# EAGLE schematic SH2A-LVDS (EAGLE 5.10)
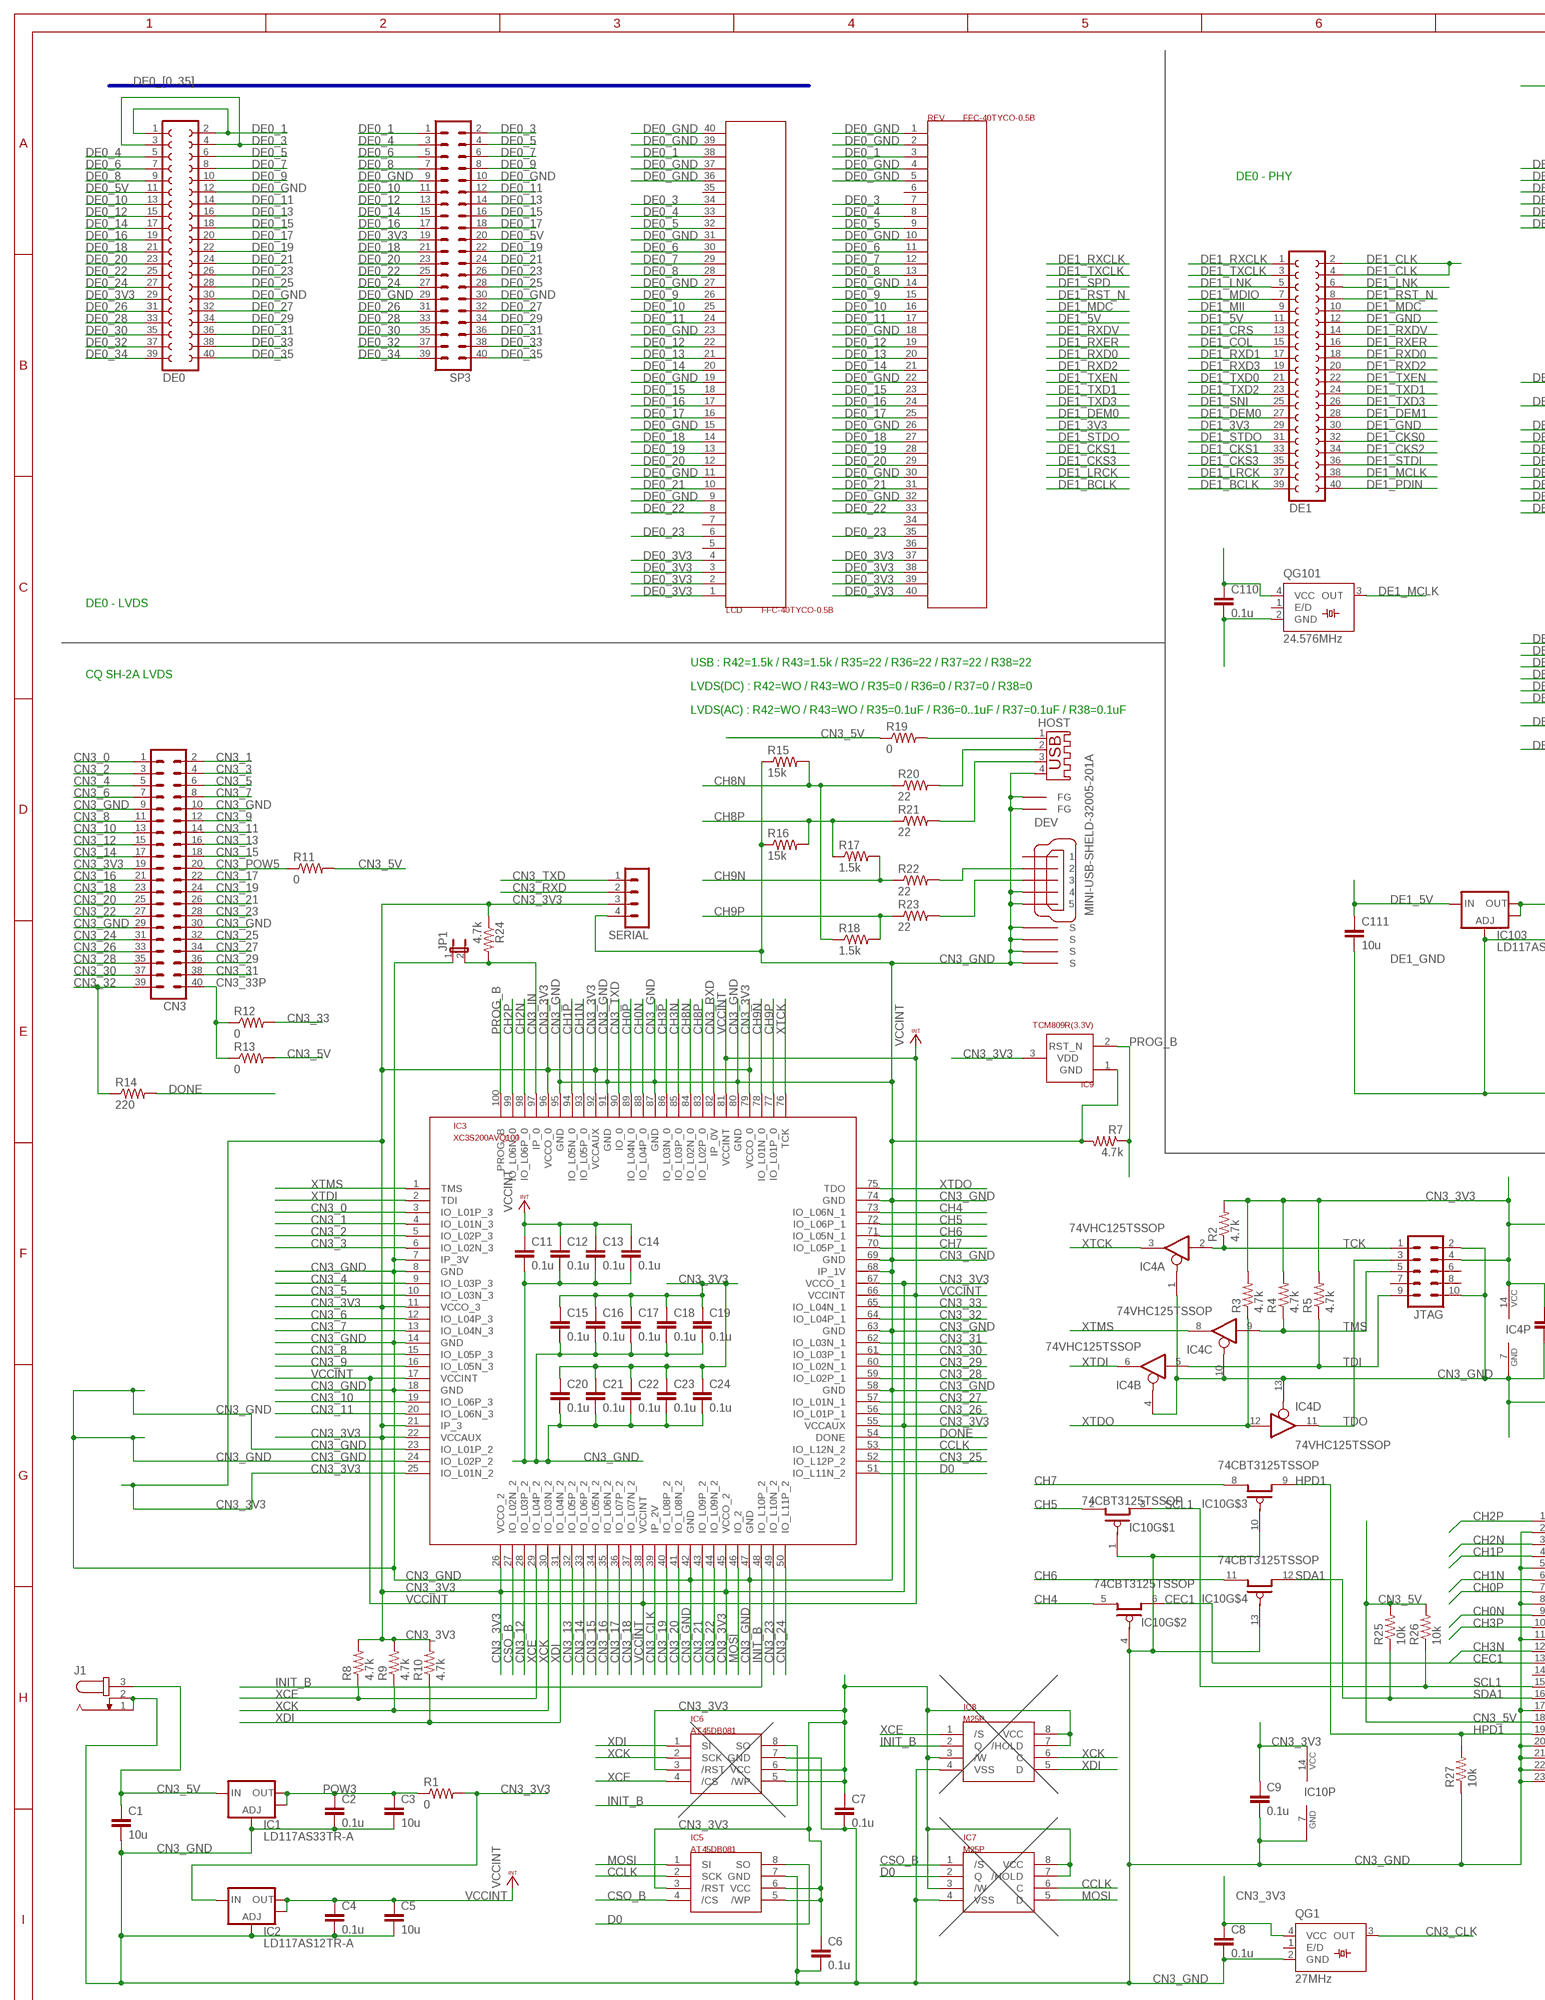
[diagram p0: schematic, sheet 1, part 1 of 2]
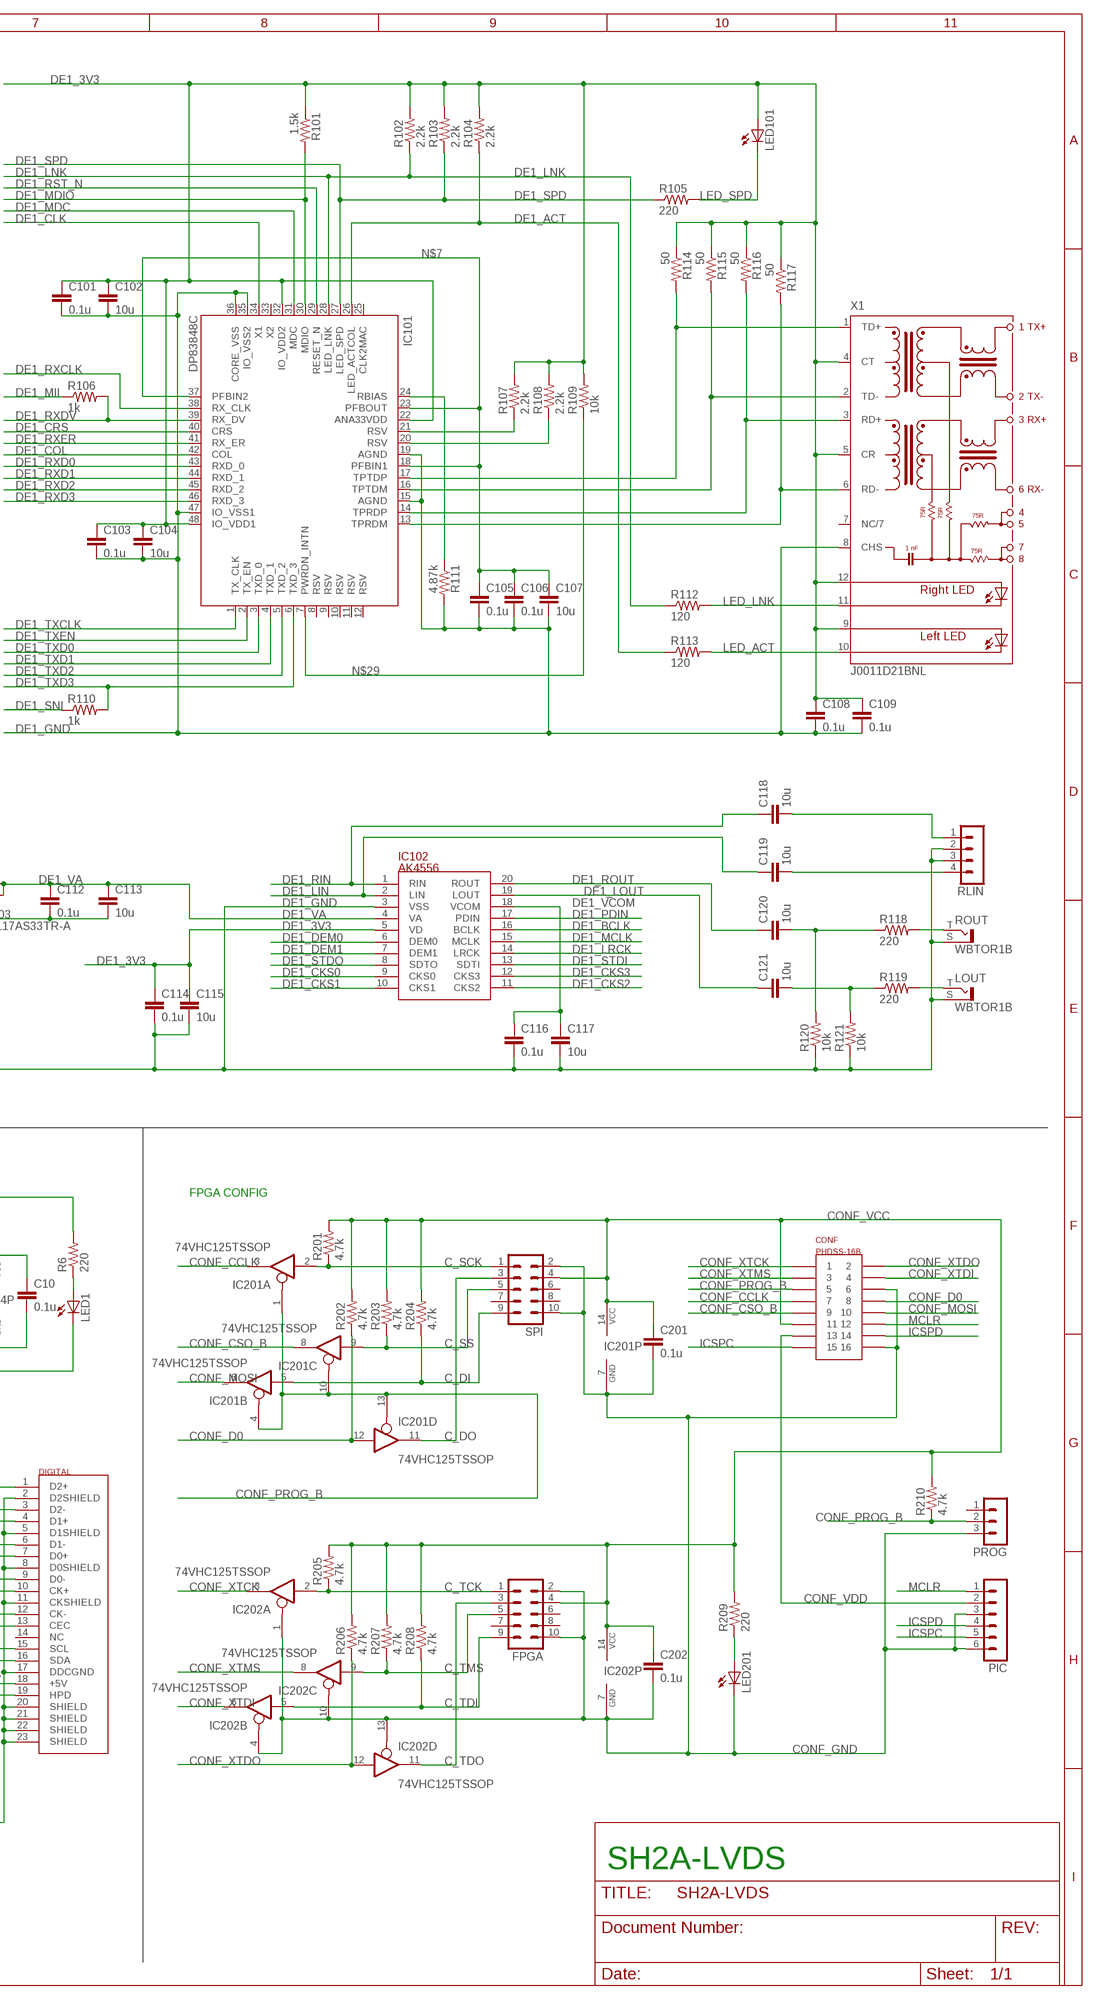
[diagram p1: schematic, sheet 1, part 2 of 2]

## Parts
C1  10u  C-EUC2012  [C2012]
C2  0.1u  C-EUC1608  [C1608]
C3  10u  C-EUC2012  [C2012]
C4  0.1u  C-EUC1608  [C1608]
C5  10u  C-EUC2012  [C2012]
C6  0.1u  C-EUC1608  [C1608]
C7  0.1u  C-EUC1608  [C1608]
C8  0.1u  C-EUC1608  [C1608]
C9  0.1u  C-EUC1608  [C1608]
C10  0.1u  C-EUC1608  [C1608]
C11  0.1u  C-EUC1608  [C1608]
C12  0.1u  C-EUC1608  [C1608]
C13  0.1u  C-EUC1608  [C1608]
C14  0.1u  C-EUC1608  [C1608]
C15  0.1u  C-EUC1608  [C1608]
C16  0.1u  C-EUC1608  [C1608]
C17  0.1u  C-EUC1608  [C1608]
C18  0.1u  C-EUC1608  [C1608]
C19  0.1u  C-EUC1608  [C1608]
C20  0.1u  C-EUC1608  [C1608]
C21  0.1u  C-EUC1608  [C1608]
C22  0.1u  C-EUC1608  [C1608]
C23  0.1u  C-EUC1608  [C1608]
C24  0.1u  C-EUC1608  [C1608]
C101  0.1u  C-EUC1608  [C1608]
C102  10u  C-EUC2012  [C2012]
C103  0.1u  C-EUC1608  [C1608]
C104  10u  C-EUC2012  [C2012]
C105  0.1u  C-EUC1608  [C1608]
C106  0.1u  C-EUC1608  [C1608]
C107  10u  C-EUC2012  [C2012]
C108  0.1u  C-EUC1608  [C1608]
C109  0.1u  C-EUC1608  [C1608]
C110  0.1u  C-EUC1608  [C1608]
C111  10u  C-EUC2012  [C2012]
C112  0.1u  C-EUC1608  [C1608]
C113  10u  C-EUC2012  [C2012]
C114  0.1u  C-EUC1608  [C1608]
C115  10u  C-EUC2012  [C2012]
C116  0.1u  C-EUC1608  [C1608]
C117  10u  C-EUC2012  [C2012]
C118  10u  C-EUC2012  [C2012]
C119  10u  C-EUC2012  [C2012]
C120  10u  C-EUC2012  [C2012]
C121  10u  C-EUC2012  [C2012]
C201  0.1u  C-EUC1608  [C1608]
C202  0.1u  C-EUC1608  [C1608]
CN3  MA20-2  [MA20-2]
CONF  PHDSS-16B  [PHDSS-16]
DE0  FE20-2  [FE20-2]
DE1  FE20-2  [FE20-2]
DEV  MINI-USB-SHELD-32005-201A  [32005-201A]
DIGITAL  HDMIHDMI-FCI-A  [HDMI-FCI-A-UPDATE]
FPGA  ML10  [ML10]
HOST  USB-A003FG  [USB]
IC1  LD117AS33TR-A  LD117AS-A  [SOT223]
IC2  LD117AS12TR-A  LD117AS-A  [SOT223]
IC3  XC3S200AVQ100  XC3S50AVQ100  [VQ100]
IC4  74VHC125TSSOP  74125TSSOP  [PW_R-PDSO-G14]
IC5  AT45DB081  AT45DB  [AT45DB]
IC6  AT45DB081  AT45DB  [AT45DB]
IC7  M25P  [AT45DB]
IC8  M25P  [AT45DB]
IC9  TCM809R(3.3V)  TCM809  [SOT23]
IC10  74CBT3125TSSOP  [PW_R-PDSO-G14]
IC101  DP83848C  [LQFP48]
IC102  AK4556  [SSOP20]
IC103  LD117AS33TR-A  LD117AS-A  [SOT223]
IC201  74VHC125TSSOP  74125TSSOP  [PW_R-PDSO-G14]
IC202  74VHC125TSSOP  74125TSSOP  [PW_R-PDSO-G14]
J1  JACK-PLUG0A  [SPC4077A]
JP1  JP1EA  [JP1A]
JTAG  ML10  [ML10]
LCD  FFC-40TYCO-0.5B  [FFC-40-0.5B-TYCO]
LED1  LED5MM  [LED5MM]
LED101  LED5MM  [LED5MM]
LED201  LED5MM  [LED5MM]
LOUT  WBTOR1B  [WBTOR1B]
PIC  MA06-1A  [MA06-1A]
PROG  MA03-1MA03-1A  [MA03-1A]
QG1  27MHz  SM77H  [SM77H]
QG101  24.576MHz  SM77H  [SM77H]
R1  0  R-US_R0603  [R0603]
R2  4.7k  R-US_R0603  [R0603]
R3  4.7k  R-US_R0603  [R0603]
R4  4.7k  R-US_R0603  [R0603]
R5  4.7k  R-US_R0603  [R0603]
R6  220  R-US_R0603  [R0603]
R7  4.7k  R-US_R0603  [R0603]
R8  4.7k  R-US_R0603  [R0603]
R9  4.7k  R-US_R0603  [R0603]
R10  4.7k  R-US_R0603  [R0603]
R11  0  R-US_R0603  [R0603]
R12  0  R-US_R0603  [R0603]
R13  0  R-US_R0603  [R0603]
R14  220  R-US_R0603  [R0603]
R15  15k  R-US_R0603  [R0603]
R16  15k  R-US_R0603  [R0603]
R17  1.5k  R-US_R0603  [R0603]
R18  1.5k  R-US_R0603  [R0603]
R19  0  R-US_R0603  [R0603]
R20  22  R-US_R0603  [R0603]
R21  22  R-US_R0603  [R0603]
R22  22  R-US_R0603  [R0603]
R23  22  R-US_R0603  [R0603]
R24  4.7k  R-US_R0603  [R0603]
R25  10k  R-US_R0603  [R0603]
R26  10k  R-US_R0603  [R0603]
R27  10k  R-US_R0603  [R0603]
R101  1.5k  R-US_R0603  [R0603]
R102  2.2k  R-US_R0603  [R0603]
R103  2.2k  R-US_R0603  [R0603]
R104  2.2k  R-US_R0603  [R0603]
R105  220  R-US_R0603  [R0603]
R106  1k  R-US_R0603  [R0603]
R107  2.2k  R-US_R0603  [R0603]
R108  2.2k  R-US_R0603  [R0603]
R109  10k  R-US_R0603  [R0603]
R110  1k  R-US_R0603  [R0603]
R111  4.87k  R-US_R0603  [R0603]
R112  120  R-US_R0603  [R0603]
R113  120  R-US_R0603  [R0603]
R114  50  R-US_R0603  [R0603]
R115  50  R-US_R0603  [R0603]
R116  50  R-US_R0603  [R0603]
R117  50  R-US_R0603  [R0603]
R118  220  R-US_R0603  [R0603]
R119  220  R-US_R0603  [R0603]
R120  10k  R-US_R0603  [R0603]
R121  10k  R-US_R0603  [R0603]
R201  4.7k  R-US_R0603  [R0603]
R202  4.7k  R-US_R0603  [R0603]
R203  4.7k  R-US_R0603  [R0603]
R204  4.7k  R-US_R0603  [R0603]
R205  4.7k  R-US_R0603  [R0603]
R206  4.7k  R-US_R0603  [R0603]
R207  4.7k  R-US_R0603  [R0603]
R208  4.7k  R-US_R0603  [R0603]
R209  220  R-US_R0603  [R0603]
R210  4.7k  R-US_R0603  [R0603]
REV  FFC-40TYCO-0.5B  [FFC-40-0.5B-TYCO]
RLIN  MA04-1A  [MA04-1A]
ROUT  WBTOR1B  [WBTOR1B]
SERIAL  MA04-1A  [MA04-1A]
SP3  MA20-2  [MA20-2]
SPI  ML10  [ML10]
X1  J0011D21BNL  [J0B]

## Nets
C_DI: IC201.5(B:I) R204.1 SPI.9
C_DO: IC201.11(D:O) SPI.3
C_SCK: IC201.2(A:I) R201.1 SPI.1
C_SS: IC201.9(C:I) R203.1 SPI.5
C_TCK: FPGA.1 IC202.2(A:I) R205.1
C_TDI: FPGA.9 IC202.5(B:I) R208.1
C_TDO: FPGA.3 IC202.11(D:O)
C_TMS: FPGA.5 IC202.9(C:I) R207.1
CCLK: IC3.53(IO_L12N_2) IC5.2(SCK) IC7.6(C)
CEC1: DIGITAL.13(CEC) IC10.6(O)
CH0N: DIGITAL.9(D0-) IC3.88(IO_L04P_0)
CH0P: DIGITAL.7(D0+) IC3.89(IO_L04N_0)
CH1N: DIGITAL.6(D1-) IC3.93(IO_L05P_0)
CH1P: DIGITAL.4(D1+) IC3.94(IO_L05N_0)
CH2N: DIGITAL.3(D2-) IC3.98(IO_L06P_0)
CH2P: DIGITAL.1(D2+) IC3.99(IO_L06N_0)
CH3N: DIGITAL.12(CK-) IC3.85(IO_L03P_0)
CH3P: DIGITAL.10(CK+) IC3.86(IO_L03N_0)
CH4: IC3.73(IO_L06N_1) IC10.5(I)
CH5: IC3.72(IO_L06P_1) IC10.2(I)
CH6: IC3.71(IO_L05N_1) IC10.11(O)
CH7: IC3.70(IO_L05P_1) IC10.8(O)
CH8N: IC3.84(IO_L02N_0) R15.2 R18.1 R20.1
CH8P: IC3.83(IO_L02P_0) R16.2 R17.1 R21.1
CH9N: IC3.78(IO_L01N_0) R17.2 R22.1
CH9P: IC3.77(IO_L01P_0) R18.2 R23.1
CN3_0: CN3.1 IC3.3(IO_L01P_3)
CN3_1: CN3.2 IC3.4(IO_L01N_3)
CN3_2: CN3.3 IC3.5(IO_L02P_3)
CN3_3: CN3.4 IC3.6(IO_L02N_3)
CN3_3V3: C6.1 C7.1 C8.1 C9.1 C10.1 C15.1 C16.1 C17.1 C18.1 C19.1 C20.1 C21.1 C22.1 C23.1 C24.1 CN3.19 IC2.3(IN) IC3.11(VCCO_3) IC3.21(IP_3) IC3.22(VCCAUX) IC3.25(IO_L01N_2) IC3.26(VCCO_2) IC3.45(VCCO_2) IC3.55(VCCAUX) IC3.67(VCCO_1) IC3.79(VCCO_0) IC3.92(VCCAUX) IC3.96(VCCO_0) IC4.14(P:VCC) IC5.3(/RST) IC5.5(/WP) IC5.6(VCC) IC6.3(/RST) IC6.5(/WP) IC6.6(VCC) IC7.3(/W) IC7.7(/HOLD) IC7.8(VCC) IC8.3(/W) IC8.7(/HOLD) IC8.8(VCC) IC9.3(VDD) IC10.14(P:VCC) JTAG.4 QG1.4(VCC) R1.2 R2.2 R3.2 R4.2 R5.2 R6.2 R8.2 R9.2 R10.2 R24.1 SERIAL.3
CN3_4: CN3.5 IC3.9(IO_L03P_3)
CN3_5: CN3.6 IC3.10(IO_L03N_3)
CN3_5V: C1.1 DIGITAL.18(+5V) IC1.3(IN) J1.3 R11.2 R13.2 R19.1 R25.2 R26.2
CN3_6: CN3.7 IC3.12(IO_L04P_3)
CN3_7: CN3.8 IC3.13(IO_L04N_3)
CN3_8: CN3.11 IC3.15(IO_L05P_3)
CN3_9: CN3.12 IC3.16(IO_L05N_3)
CN3_10: CN3.13 IC3.19(IO_L06P_3)
CN3_11: CN3.14 IC3.20(IO_L06N_3)
CN3_12: CN3.15 IC3.28(IO_L03P_2)
CN3_13: CN3.16 IC3.32(IO_L05P_2)
CN3_14: CN3.17 IC3.33(IO_L06P_2)
CN3_15: CN3.18 IC3.34(IO_L05N_2)
CN3_16: CN3.21 IC3.35(IO_L06N_2)
CN3_17: CN3.22 IC3.36(IO_L07P_2)
CN3_18: CN3.23 IC3.37(IO_L07N_2)
CN3_19: CN3.24 IC3.40(IO_L08P_2)
CN3_20: CN3.25 IC3.41(IO_L08N_2)
CN3_21: CN3.26 IC3.43(IO_L09P_2)
CN3_22: CN3.27 IC3.44(IO_L09N_2)
CN3_23: CN3.28 IC3.49(IO_L10N_2)
CN3_24: CN3.31 IC3.50(IO_L11P_2)
CN3_25: CN3.32 IC3.52(IO_L12P_2)
CN3_26: CN3.33 IC3.56(IO_L01P_1)
CN3_27: CN3.34 IC3.57(IO_L01N_1)
CN3_28: CN3.35 IC3.59(IO_L02P_1)
CN3_29: CN3.36 IC3.60(IO_L02N_1)
CN3_30: CN3.37 IC3.61(IO_L03P_1)
CN3_31: CN3.38 IC3.62(IO_L03N_1)
CN3_32: CN3.39 IC3.64(IO_L04P_1) R14.1
CN3_33: IC3.65(IO_L04N_1) R12.2
CN3_33P: CN3.40 R12.1 R13.1
CN3_CLK: IC3.39(IP_2V) QG1.3(OUT)
CN3_GND: C1.2 C2.2 C3.2 C4.2 C5.2 C6.2 C7.2 C8.2 C9.2 C10.2 C11.2 C12.2 C13.2 C14.2 C15.2 C16.2 C17.2 C18.2 C19.2 C20.2 C21.2 C22.2 C23.2 C24.2 CN3.9 CN3.10 CN3.29 CN3.30 DEV.4 DEV.5 DEV.M1(S) DEV.M2(S) DEV.M3(S) DEV.M4(S) DIGITAL.2(D2SHIELD) DIGITAL.5(D1SHIELD) DIGITAL.8(D0SHIELD) DIGITAL.11(CKSHIELD) DIGITAL.17(DDCGND) DIGITAL.20(SHIELD) DIGITAL.21(SHIELD) DIGITAL.22(SHIELD) DIGITAL.23(SHIELD) HOST.4 HOST.P$1(FG) HOST.P$2(FG) IC1.1(ADJ) IC2.1(ADJ) IC3.7(IP_3V) IC3.8(GND) IC3.14(GND) IC3.18(GND) IC3.23(IO_L01P_2) IC3.24(IO_L02P_2) IC3.42(GND) IC3.47(GND) IC3.58(GND) IC3.63(GND) IC3.68(IP_1V) IC3.69(GND) IC3.74(GND) IC3.80(GND) IC3.87(GND) IC3.91(GND) IC3.95(GND) IC4.1(A:OE) IC4.4(B:OE) IC4.7(P:GND) IC4.10(C:OE) IC4.13(D:OE) IC5.7(GND) IC6.7(GND) IC7.4(VSS) IC8.4(VSS) IC9.1(GND) IC10.1(OE) IC10.4(OE) IC10.7(P:GND) IC10.10(OE) IC10.13(OE) J1.1 J1.2 JP1.1 JTAG.2 JTAG.10 LED1.K(C) QG1.2(GND) R7.2 R15.1 R16.1 R27.1 SERIAL.4
CN3_IN: IC3.97(IP_0) JP1.2 R24.2
CN3_POW5: CN3.20 R11.1
CN3_RXD: IC3.82(IP_0V) SERIAL.2
CN3_TXD: IC3.90(IO_0) SERIAL.1
CONF_CCLK: CONF.P$7 IC201.3(A:O)
CONF_CSO_B: CONF.P$9 IC201.8(C:O)
CONF_D0: CONF.P$8 IC201.12(D:I) R202.1
CONF_GND: C201.2 C202.2 CONF.P$6 CONF.P$16 FPGA.2 FPGA.10 IC201.7(P:GND) IC202.1(A:OE) IC202.4(B:OE) IC202.7(P:GND) IC202.10(C:OE) IC202.13(D:OE) LED201.K(C) PIC.3 PIC.6 PROG.3 SPI.2 SPI.10
CONF_MOSI: CONF.P$10 IC201.6(B:O)
CONF_PROG_B: CONF.P$5 IC201.1(A:OE) IC201.4(B:OE) IC201.10(C:OE) IC201.13(D:OE) PROG.2 R210.1
CONF_VCC: C201.1 C202.1 CONF.P$11 FPGA.4 IC201.14(P:VCC) IC202.14(P:VCC) R201.2 R202.2 R203.2 R204.2 R205.2 R206.2 R207.2 R208.2 R209.2 R210.2 SPI.4
CONF_VDD: CONF.P$13 PIC.2
CONF_XTCK: CONF.P$1 IC202.3(A:O)
CONF_XTDI: CONF.P$4 IC202.6(B:O)
CONF_XTDO: CONF.P$2 IC202.12(D:I) R206.1
CONF_XTMS: CONF.P$3 IC202.8(C:O)
CSO_B: IC3.27(IO_L02N_2) IC5.4(/CS) IC7.1(/S)
D0: IC3.51(IO_L11N_2) IC5.8(SO) IC7.2(Q)
DE0_1: DE0.1 DE0.2 LCD.38 REV.3 SP3.1
DE0_3: DE0.3 DE0.4 LCD.34 REV.7 SP3.2
DE0_3V3: DE0.29 LCD.1 LCD.2 LCD.3 LCD.4 REV.37 REV.38 REV.39 REV.40 SP3.19
DE0_4: DE0.5 LCD.33 REV.8 SP3.3
DE0_5: DE0.6 LCD.32 REV.9 SP3.4
DE0_5V: DE0.11 SP3.20
DE0_6: DE0.7 LCD.30 REV.11 SP3.5
DE0_7: DE0.8 LCD.29 REV.12 SP3.6
DE0_8: DE0.9 LCD.28 REV.13 SP3.7
DE0_9: DE0.10 LCD.26 REV.15 SP3.8
DE0_10: DE0.13 LCD.25 REV.16 SP3.11
DE0_11: DE0.14 LCD.24 REV.17 SP3.12
DE0_12: DE0.15 LCD.22 REV.19 SP3.13
DE0_13: DE0.16 LCD.21 REV.20 SP3.14
DE0_14: DE0.17 LCD.20 REV.21 SP3.15
DE0_15: DE0.18 LCD.18 REV.23 SP3.16
DE0_16: DE0.19 LCD.17 REV.24 SP3.17
DE0_17: DE0.20 LCD.16 REV.25 SP3.18
DE0_18: DE0.21 LCD.14 REV.27 SP3.21
DE0_19: DE0.22 LCD.13 REV.28 SP3.22
DE0_20: DE0.23 LCD.12 REV.29 SP3.23
DE0_21: DE0.24 LCD.10 REV.31 SP3.24
DE0_22: DE0.25 LCD.8 REV.33 SP3.25
DE0_23: DE0.26 LCD.6 REV.35 SP3.26
DE0_24: DE0.27 SP3.27
DE0_25: DE0.28 SP3.28
DE0_26: DE0.31 SP3.31
DE0_27: DE0.32 SP3.32
DE0_28: DE0.33 SP3.33
DE0_29: DE0.34 SP3.34
DE0_30: DE0.35 SP3.35
DE0_31: DE0.36 SP3.36
DE0_32: DE0.37 SP3.37
DE0_33: DE0.38 SP3.38
DE0_34: DE0.39 SP3.39
DE0_35: DE0.40 SP3.40
DE0_GND: DE0.12 DE0.30 LCD.9 LCD.11 LCD.15 LCD.19 LCD.23 LCD.27 LCD.31 LCD.36 LCD.37 LCD.39 LCD.40 REV.1 REV.2 REV.4 REV.5 REV.10 REV.14 REV.18 REV.22 REV.26 REV.30 REV.32 SP3.9 SP3.10 SP3.29 SP3.30
DE1_3V3: C101.1 C102.1 C103.1 C104.1 C108.1 C109.1 C110.1 C114.1 C115.1 DE1.29 IC101.22(ANA33VDD) IC101.32(IO_VDD2) IC101.48(IO_VDD1) IC102.5(VD) LED101.A QG101.4(VCC) R101.1 R102.2 R103.2 R104.2 R107.2 R108.2 R109.2 R114.1 R115.1 R116.1 R117.1 X1.4(CT) X1.5(CR) X1.9(A-L) X1.12(A-R)
DE1_5V: C111.1 DE1.11 IC103.3(IN)
DE1_ACT: IC101.26(LED_ACTCOL) R104.1 R113.1
DE1_BCLK: DE1.39 IC102.16(BCLK)
DE1_CKS0: DE1.32 IC102.9(CKS0)
DE1_CKS1: DE1.33 IC102.10(CKS1)
DE1_CKS2: DE1.34 IC102.11(CKS2)
DE1_CKS3: DE1.35 IC102.12(CKS3)
DE1_CLK: DE1.2 DE1.4 IC101.34(X1)
DE1_COL: DE1.15 IC101.42(COL)
DE1_CRS: DE1.13 IC101.40(CRS)
DE1_DEM0: DE1.27 IC102.6(DEM0)
DE1_DEM1: DE1.28 IC102.7(DEM1)
DE1_GND: C101.2 C102.2 C103.2 C104.2 C105.2 C106.2 C107.2 C108.2 C109.2 C110.2 C111.2 C112.2 C113.2 C114.2 C115.2 C116.2 C117.2 DE1.12 DE1.30 IC101.15(AGND) IC101.19(AGND) IC101.35(IO_VSS2) IC101.36(CORE_VSS) IC101.47(IO_VSS1) IC102.3(VSS) IC103.1(ADJ) LOUT.S QG101.2(GND) R111.2 R120.1 R121.1 RLIN.2 RLIN.3 ROUT.S X1.8(CHS)
DE1_LIN: C119.1 IC102.2(LIN)
DE1_LNK: DE1.5 DE1.6 IC101.28(LED_LNK) R102.1 R112.1
DE1_LOUT: C121.1 IC102.19(LOUT)
DE1_LRCK: DE1.37 IC102.14(LRCK)
DE1_MCLK: DE1.38 IC102.15(MCLK) QG101.3(OUT)
DE1_MDC: DE1.10 IC101.31(MDC)
DE1_MDIO: DE1.7 IC101.30(MDIO) R101.2
DE1_MII: DE1.9 R106.1
DE1_PDIN: DE1.40 IC102.17(PDIN)
DE1_RIN: C118.1 IC102.1(RIN)
DE1_ROUT: C120.1 IC102.20(ROUT)
DE1_RST_N: DE1.8 IC101.29(RESET_N)
DE1_RXCLK: DE1.1 IC101.38(RX_CLK)
DE1_RXD0: DE1.18 IC101.43(RXD_0)
DE1_RXD1: DE1.17 IC101.44(RXD_1)
DE1_RXD2: DE1.20 IC101.45(RXD_2)
DE1_RXD3: DE1.19 IC101.46(RXD_3)
DE1_RXDV: DE1.14 IC101.39(RX_DV) R106.2
DE1_RXER: DE1.16 IC101.41(RX_ER)
DE1_SNI: DE1.25 R110.1
DE1_SPD: IC101.27(LED_SPD) R103.1 R105.1
DE1_STDI: DE1.36 IC102.13(SDTI)
DE1_STDO: DE1.31 IC102.8(SDTO)
DE1_TXCLK: DE1.3 IC101.1(TX_CLK)
DE1_TXD0: DE1.21 IC101.3(TXD_0)
DE1_TXD1: DE1.24 IC101.4(TXD_1)
DE1_TXD2: DE1.23 IC101.5(TXD_2)
DE1_TXD3: DE1.26 IC101.6(TXD_3) R110.2
DE1_TXEN: DE1.22 IC101.2(TX_EN)
DE1_VA: C112.1 C113.1 IC102.4(VA) IC103.2(OUT) IC103.4(OUT)
DE1_VCOM: C116.1 C117.1 IC102.18(VCOM)
DONE: IC3.54(DONE) R14.2
HPD1: DIGITAL.19(HPD) IC10.9(I) R27.2
ICSPC: CONF.P$15 PIC.5
ICSPD: CONF.P$14 PIC.4
INIT_B: IC3.48(IO_L10P_2) IC6.8(SO) IC8.2(Q)
LED_ACT: R113.2 X1.10(C-L)
LED_LNK: R112.2 X1.11(C-R)
LED_SPD: LED101.K(C) R105.2
MCLR: CONF.P$12 PIC.1
MOSI: IC3.46(IO_2) IC5.1(SI) IC7.5(D)
N$1: C118.2 RLIN.1
N$2: HOST.1 R19.2
N$3: LED201.A R209.1
N$4: HOST.2 R20.2
N$5: HOST.3 R21.2
N$6: DEV.2 R22.2
N$7: C105.1 C106.1 C107.1 IC101.18(PFBIN1) IC101.23(PFBOUT) IC101.37(PFBIN2)
N$9: DEV.3 R23.2
N$10: LED1.A R6.1
N$14: IC101.17(TPTDP) R114.2 X1.1(TD+)
N$15: IC101.16(TPTDM) R115.2 X1.2(TD-)
N$16: IC101.14(TPRDP) R116.2 X1.3(RD+)
N$17: C119.2 RLIN.4
N$18: R118.2 ROUT.T
N$19: LOUT.T R119.2
N$21: C121.2 R119.1 R121.2
N$22: IC101.13(TPRDM) R117.2 X1.6(RD-)
N$23: C120.2 R118.1 R120.2
N$29: IC101.7(PWRDN_INTN) R109.1
N$43: IC101.24(RBIAS) R111.1
N$44: IC101.21(RSV) R107.1
N$45: IC101.20(RSV) R108.1
POW3: C2.1 C3.1 IC1.2(OUT) IC1.4(OUT) R1.1
PROG_B: IC3.100(PROG_B) IC9.2(RST_N) R7.1
SCL1: DIGITAL.15(SCL) IC10.3(O) R26.1
SDA1: DIGITAL.16(SDA) IC10.12(I) R25.1
TCK: IC4.2(A:I) JTAG.1 R2.1
TDI: IC4.5(B:I) JTAG.9 R5.1
TDO: IC4.11(D:O) JTAG.3
TMS: IC4.9(C:I) JTAG.5 R4.1
VCCINT: C4.1 C5.1 C11.1 C12.1 C13.1 C14.1 IC2.2(OUT) IC2.4(OUT) IC3.17(VCCINT) IC3.38(VCCINT) IC3.66(VCCINT) IC3.81(VCCINT)
XCE: IC3.29(IO_L04P_2) IC6.4(/CS) IC8.1(/S) R8.1
XCK: IC3.30(IO_L03N_2) IC6.2(SCK) IC8.6(C) R9.1
XDI: IC3.31(IO_L04N_2) IC6.1(SI) IC8.5(D) R10.1
XTCK: IC3.76(TCK) IC4.3(A:O)
XTDI: IC3.2(TDI) IC4.6(B:O)
XTDO: IC3.75(TDO) IC4.12(D:I) R3.1
XTMS: IC3.1(TMS) IC4.8(C:O)
Unconnected: DEV.1 DIGITAL.14(NC) FPGA.6 FPGA.7 FPGA.8 IC101.8(RSV) IC101.9(RSV) IC101.10(RSV) IC101.11(RSV) IC101.12(RSV) IC101.25(CLK2MAC) IC101.33(X2) JTAG.6 JTAG.7 JTAG.8 LCD.5 LCD.7 LCD.35 PROG.1 QG1.1(E/D) QG101.1(E/D) REV.6 REV.34 REV.36 SPI.6 SPI.7 SPI.8 X1.7(NC/7)

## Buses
DE0_[0..35]

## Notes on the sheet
- DE0 - PHY
- DE0 - LVDS
- USB : R42=1.5k / R43=1.5k / R35=22 / R36=22 / R37=22 / R38=22
- CQ SH-2A LVDS
- LVDS(DC) : R42=WO / R43=WO / R35=0 / R36=0 / R37=0 / R38=0
- LVDS(AC) : R42=WO / R43=WO / R35=0.1uF / R36=0..1uF / R37=0.1uF / R38=0.1uF
- FPGA CONFIG
- SH2A-LVDS

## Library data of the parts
C1-C24 C101-C121 C201 C202 = adcr:C-EU: CAPACITOR, European symbol
CN3 SP3 = adcr:MA20-2: PIN HEADER
CONF = adcr:PHDSS-16
DE0 DE1 = con-lsta:FE20-2: FEMALE HEADER
DEV = adcr:MINI-USB-SHELD-
DIGITAL = adcr:HDMI
FPGA JTAG SPI = con-ml:ML10: HARTING
HOST = adcr:USB-A003: USB connector
IC1 IC2 IC103 = adcr:LD117A?*-A
IC3 = adcr:XC3S50AVQ100
IC4 IC201 IC202 = adcr:74*125: Quad bus BUFFER, 3-state
IC5 IC6 = adcr:AT45DB
IC7 IC8 = adcr:M25P
IC9 = adcr:TCM809
IC10 = adcr:74CBT3125
IC101 = adcr:DP83848C
IC102 = adcr:AK4556
J1 = adcr:JACK-PLUG: DC POWER JACK Power Jack, DC, Right Angle, Through Hole, Rated 5A at 16VDC, PC Terminals Distributor: Farnell (www.Farnell.de) Drawing: 84N1161.pdf / 84N1162.pdf Manufacturer: SPC Technology (www.spctechnology.com) Type: SPC4077 / SPC 4078
JP1 = adcr:JP1E: JUMPER
LCD REV = adcr:FFC-40
LED1 LED101 LED201 = adcr:LED: LED
LOUT ROUT = adcr:WBTOR1: RCA connectors according to JEITA RC-5231 Cinch
PIC = adcr:MA06-1: PIN HEADER
PROG = adcr:MA03-1: PIN HEADER
QG1 QG101 = adcr:SM77H: 3.3V CMOS Clock Oscillator Source: www.pletronics.com .. sm77h%203.3v.pdf
R1-R27 R101-R121 R201-R210 = adcr:R-US_: RESISTOR, American symbol
RLIN SERIAL = adcr:MA04-1: PIN HEADER
X1 = adcr:J0011D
